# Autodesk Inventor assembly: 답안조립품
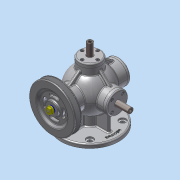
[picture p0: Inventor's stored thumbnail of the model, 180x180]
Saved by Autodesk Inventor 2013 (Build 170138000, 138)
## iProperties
Created: 2016-07
Part Number: 답안조립품
Document SubType Name: Assembly
Designer: Administrator
Author: Administrator
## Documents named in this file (17)
- C:\Users\Administrator\Desktop\360708V1031\답안조립품.iam
- C:\Users\Administrator\Desktop\360708V1031\본체.ipt
- C:\Users\Administrator\Desktop\360708V1031\V-벨트풀리.ipt
- C:\Users\Administrator\Desktop\360708V1031\너트-M8x1.ipt
- C:\Users\Administrator\Desktop\360708V1031\뒤커버.ipt
- C:\Users\Administrator\Desktop\360708V1031\베어링- 6202.ipt
- C:\Users\Administrator\Desktop\360708V1031\본체커버.ipt
- C:\Users\Administrator\Desktop\360708V1031\볼트 M4x0.7.ipt
- C:\Users\Administrator\Desktop\360708V1031\스프링1.ipt
- C:\Users\Administrator\Desktop\360708V1031\스프링2.ipt
- C:\Users\Administrator\Desktop\360708V1031\슬라이드 커버.ipt
- C:\Users\Administrator\Desktop\360708V1031\슬라이드.ipt
- C:\Users\Administrator\Desktop\360708V1031\앞커버.ipt
- C:\Users\Administrator\Desktop\360708V1031\오일실.ipt
- C:\Users\Administrator\Desktop\360708V1031\와셔 8x17.ipt
- C:\Users\Administrator\Desktop\360708V1031\축.ipt
- C:\Users\Administrator\Desktop\360708V1031\키-4x4.ipt
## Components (18 placed, 2 different names)
1. V-벨트풀리:1
2. M4x0.7x12:17
3. M4x0.7x12:3
4. M4x0.7x12:5
5. M4x0.7x12:6
6. M4x0.7x12:7
7. M4x0.7x12:4
8. M4x0.7x12:8
9. M4x0.7x12:9
10. M4x0.7x12:10
11. M4x0.7x12:2
12. M4x0.7x12:11
13. M4x0.7x12:12
14. M4x0.7x12:13
15. M4x0.7x12:1
16. M4x0.7x12:14
17. M4x0.7x12:15
18. M4x0.7x12:16
